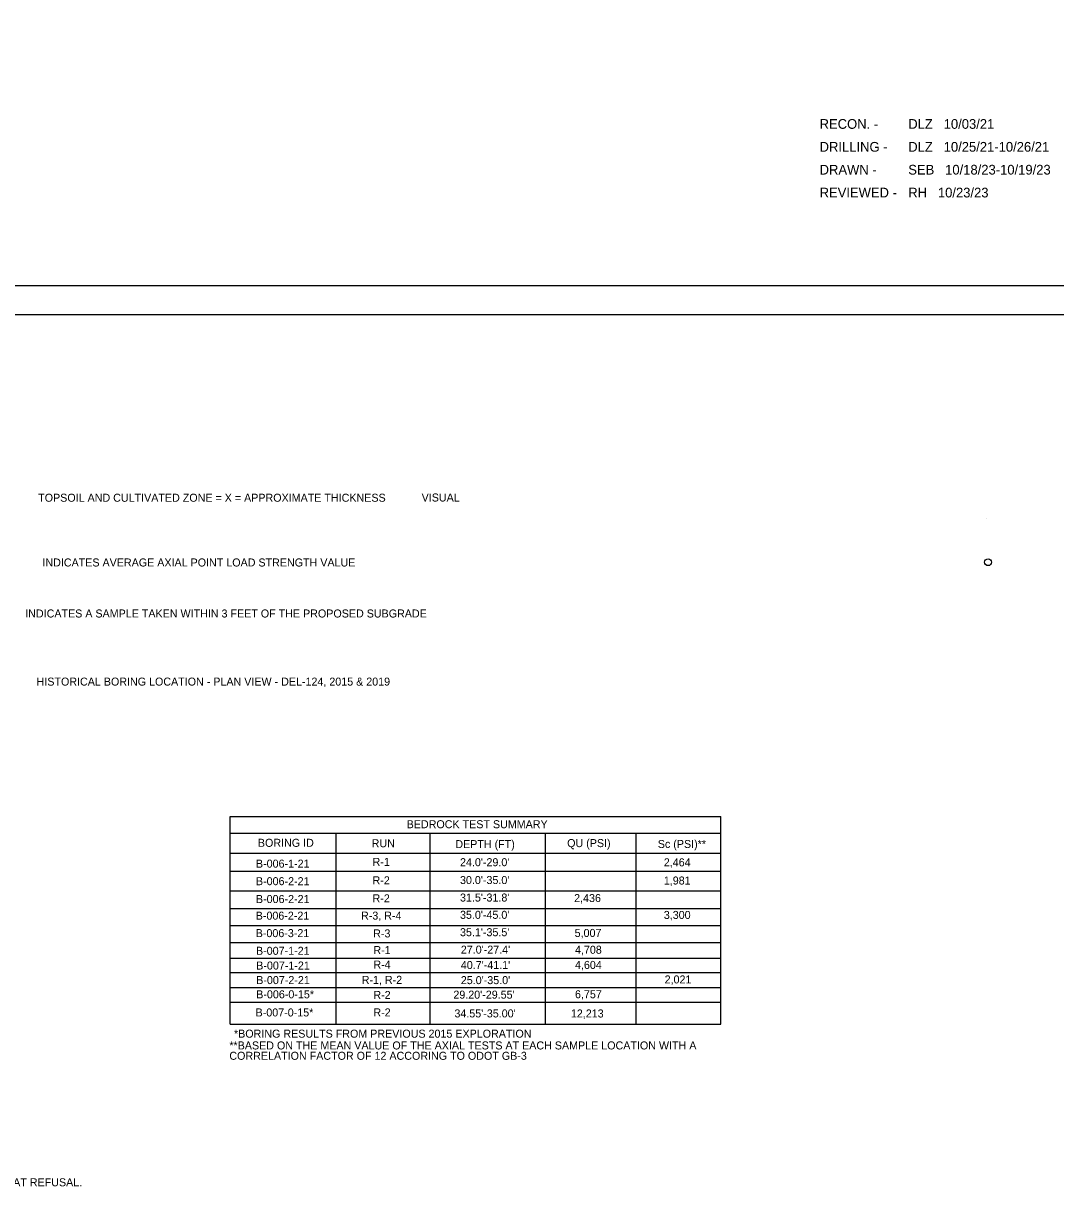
# Model space of a CAD drawing. Extents: x -11.4 to 84.1, y 11.1 to 59.
# Drawn here: x 14.02 to 32.07, y 11.14 to 31.52 of the extents above; entities that cross this region are included whole.
import ezdxf

# ---------------------------------------------------------------- set-up
doc = ezdxf.new("R2010")
doc.units = 0
for name, color, linetype in [('SH_Border', 7, 'Continuous'), ('SH_Cut_Line', 7, 'Continuous'), ('SH_Data', 7, 'Continuous'), ('SH_Text', 7, 'Continuous')]:
    doc.layers.add(name, color=color, linetype=linetype)

msp = doc.modelspace()

# ---------------------------------------------------------------- linework, layer by layer
at = {"layer": 'SH_Border'}
msp.add_lwpolyline([(4.289, 47.929), (36.289, 47.929), (36.289, 26.929), (4.289, 26.929)], close=True, dxfattribs=at)
at = {"layer": 'SH_Cut_Line'}
msp.add_lwpolyline([(2.789, 26.429), (36.789, 26.429), (36.789, 48.429), (2.789, 48.429)], close=True, dxfattribs=at)
msp.add_circle((30.883, 22.094), 0.0594, dxfattribs=at)
at = {"layer": 'SH_Data'}
for p, q in [((17.635, 14.016), (17.635, 17.648)), ((17.635, 17.648), (26.209, 17.648)), ((26.209, 14.016), (26.209, 17.646)), ((17.635, 17.355), (26.209, 17.355)), ((19.484, 14.016), (19.484, 17.353)), ((21.131, 14.016), (21.131, 17.355)), ((23.147, 14.016), (23.147, 17.348)), ((24.734, 14.016), (24.734, 17.351)), ((17.635, 17.008), (26.209, 17.008)), ((17.635, 16.694), (26.209, 16.694)), ((17.635, 16.35), (26.209, 16.35)), ((17.635, 16.042), (26.209, 16.042)), ((17.635, 15.74), (26.209, 15.74)), ((17.635, 15.447), (26.209, 15.447)), ((17.635, 15.172), (26.209, 15.172)), ((17.635, 14.919), (26.209, 14.919)), ((17.635, 14.656), (26.209, 14.656)), ((17.635, 14.402), (26.209, 14.402)), ((17.635, 14.016), (26.209, 14.016))]:
    msp.add_line(p, q, dxfattribs=at)
at = {"layer": 'SH_Text'}
msp.add_line((30.857, 22.854), (30.857, 22.854), dxfattribs=at)

# ---------------------------------------------------------------- texts
for s, height, p in [('RECON. -', 0.17, (27.939, 29.673)), ('DLZ   10/03/21           ', 0.17, (29.489, 29.673)), ('DRILLING -', 0.17, (27.939, 29.273)), ('DLZ   10/25/21-10/26/21  ', 0.17, (29.489, 29.273)), ('DRAWN -', 0.17, (27.939, 28.873)), ('SEB   10/18/23-10/19/23                 ', 0.17, (29.489, 28.873)), ('REVIEWED -', 0.17, (27.939, 28.473)), ('RH   10/23/23                           ', 0.17, (29.489, 28.473)), ('TOPSOIL AND CULTIVATED ZONE = X = APPROXIMATE THICKNESS', 0.14, (14.277, 23.152)), ('VISUAL ', 0.14, (20.981, 23.156)), ('INDICATES AVERAGE AXIAL POINT LOAD STRENGTH VALUE', 0.14, (14.351, 22.02)), ('INDICATES A SAMPLE TAKEN WITHIN 3 FEET OF THE PROPOSED SUBGRADE', 0.14, (14.05, 21.128)), ('HISTORICAL BORING LOCATION - PLAN VIEW - DEL-124, 2015 & 2019', 0.14, (14.249, 19.937)), ('BEDROCK TEST SUMMARY', 0.14, (20.719, 17.443)), ('BORING ID', 0.14, (18.118, 17.118)), ('RUN', 0.14, (20.107, 17.11)), ('DEPTH (FT)', 0.14, (21.57, 17.095)), ('QU (PSI)', 0.14, (23.525, 17.113)), ('Sc (PSI)**', 0.14, (25.11, 17.098)), ('R-1', 0.14, (20.123, 16.785)), ("24.0'-29.0'", 0.14, (21.652, 16.779)), ('2,464', 0.14, (25.215, 16.777)), ('B-006-1-21', 0.14, (18.084, 16.754)), ('B-006-2-21', 0.14, (18.084, 16.447)), ('R-2', 0.14, (20.123, 16.462)), ("30.0'-35.0'", 0.14, (21.652, 16.467)), ('1,981', 0.14, (25.215, 16.459)), ("31.5'-31.8'", 0.14, (21.652, 16.161)), ('B-006-2-21', 0.14, (18.084, 16.135)), ('R-2', 0.14, (20.123, 16.147)), ('2,436', 0.14, (23.647, 16.152)), ('B-006-2-21', 0.14, (18.08, 15.844)), ('R-3, R-4', 0.14, (19.921, 15.845)), ("35.0'-45.0'", 0.14, (21.652, 15.859)), ('3,300', 0.14, (25.215, 15.857)), ("35.1'-35.5'", 0.14, (21.652, 15.555)), ('B-006-3-21', 0.14, (18.08, 15.539)), ('R-3', 0.14, (20.133, 15.534)), ('5,007', 0.14, (23.656, 15.542)), ('B-007-1-21', 0.14, (18.085, 15.23)), ('R-1', 0.14, (20.137, 15.243)), ("27.0'-27.4'", 0.14, (21.666, 15.25)), ('4,708', 0.14, (23.662, 15.248)), ('B-007-1-21', 0.14, (18.089, 14.972)), ('R-4', 0.14, (20.137, 14.99)), ("40.7'-41.1'", 0.14, (21.666, 14.981)), ('4,604', 0.14, (23.662, 14.983)), ('B-007-2-21', 0.14, (18.089, 14.718)), ('R-1, R-2', 0.14, (19.933, 14.722)), ("25.0'-35.0'", 0.14, (21.666, 14.717)), ('2,021', 0.14, (25.229, 14.729)), ('B-006-0-15*', 0.14, (18.089, 14.469)), ('R-2', 0.14, (20.137, 14.458)), ("29.20'-29.55'", 0.14, (21.536, 14.463)), ('6,757', 0.14, (23.662, 14.47)), ('B-007-0-15*', 0.14, (18.078, 14.152)), ('R-2', 0.14, (20.137, 14.153)), ("34.55'-35.00'", 0.14, (21.554, 14.135)), ('12,213', 0.14, (23.59, 14.134)), ('*BORING RESULTS FROM PREVIOUS 2015 EXPLORATION', 0.14, (17.7, 13.781)), ('**BASED ON THE MEAN VALUE OF THE AXIAL TESTS AT EACH SAMPLE LOCATION WITH A ', 0.14, (17.619, 13.575)), ('CORRELATION FACTOR OF 12 ACCORING TO ODOT GB-3', 0.14, (17.619, 13.394)), ('Y/D"= NUMBER OF BLOWS (UNCORRECTED) FOR D" OF PENETRATION AT REFUSAL.', 0.14, (7.367, 11.182))]:
    msp.add_text(s, height=height, dxfattribs=at).set_placement(p)

doc.saveas('drawing.dxf')
